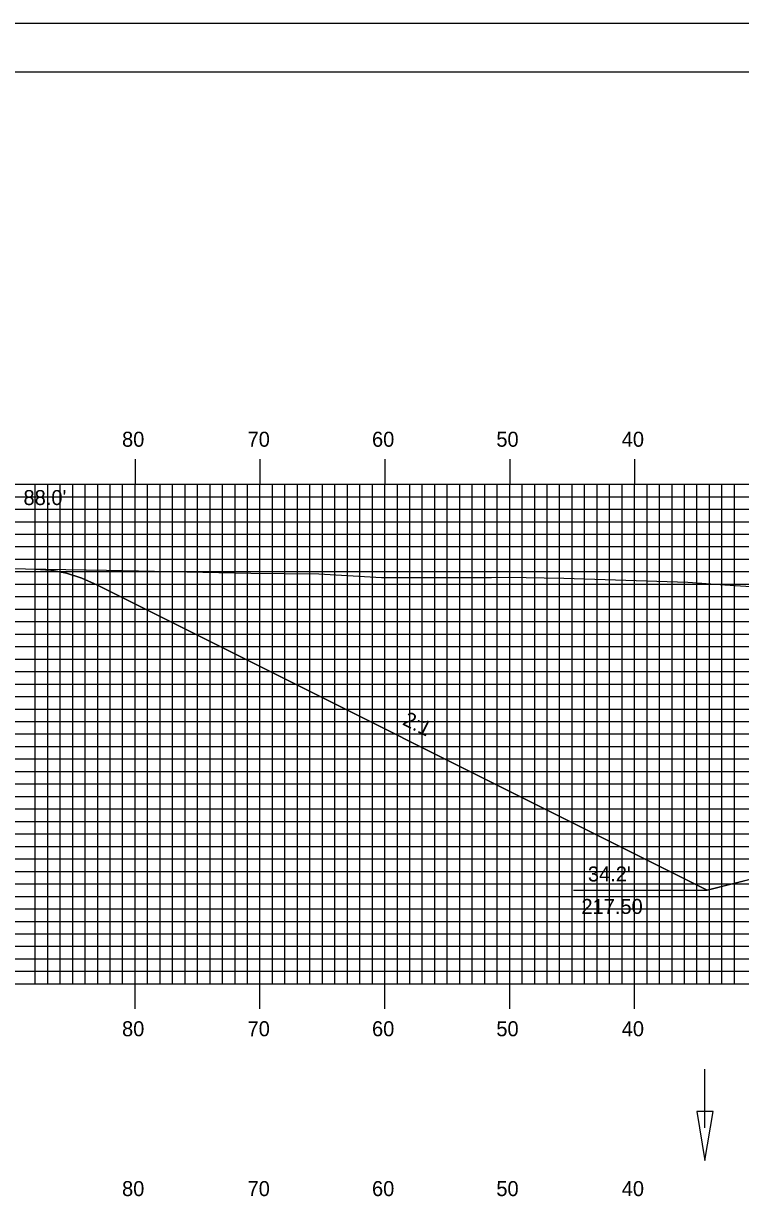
# Model space of a CAD drawing. Extents: x 1816489 to 1816833, y 442591 to 442811.
# Drawn here: x 1816566.1 to 1816623.6, y 442716.2 to 442810.5 of the extents above; entities that cross this region are included whole.
import ezdxf

# ---------------------------------------------------------------- set-up
doc = ezdxf.new("R2010")
doc.units = 0
for name, color, linetype in [('ANNOTATION', 7, 'Continuous'), ('BORDER', 7, 'Continuous'), ('D_Drainage_Ditch_Line', 7, 'Continuous'), ('D_Roadway_Centerline', 7, 'Continuous'), ('D_Roadway_SlopeLines', 7, 'Continuous'), ('D_Text_Standard', 7, 'Continuous'), ('H_V ANNOTATION', 7, 'Continuous'), ('MAJOR', 7, 'Continuous'), ('MINOR', 7, 'Continuous'), ('PDRAIN', 7, 'Continuous'), ('PLOT BOUNDARY', 7, 'Continuous'), ('S_Roadway_Centerline', 7, 'Continuous')]:
    doc.layers.add(name, color=color, linetype=linetype)

msp = doc.modelspace()

# ---------------------------------------------------------------- linework, layer by layer
at = {"layer": 'BORDER'}
msp.add_lwpolyline([(1816505.473, 442596.665), (1816825.473, 442596.665), (1816825.473, 442806.665), (1816505.473, 442806.665)], close=True, dxfattribs=at)
at = {"layer": 'D_Drainage_Ditch_Line'}
msp.add_line((1816620.707, 442722.133), (1816620.707, 442726.832), dxfattribs=at)
msp.add_lwpolyline([(1816621.363, 442723.445), (1816620.051, 442723.445), (1816620.707, 442719.508)], close=True, dxfattribs=at)
at = {"layer": 'D_Roadway_Centerline'}
msp.add_lwpolyline([(1816567.063, 442766.87), (1816568.313, 442766.776), (1816569.563, 442766.53), (1816570.813, 442766.133), (1816572.063, 442765.584), (1816620.899, 442741.166), (1816624.899, 442742.166), (1816635.073, 442744.709), (1816643.073, 442745.029), (1816655.073, 442745.269), (1816667.073, 442745.029), (1816675.073, 442744.709), (1816685.247, 442742.166), (1816689.247, 442741.166), (1816725.957, 442759.521), (1816727.207, 442760.056), (1816728.457, 442760.411), (1816729.707, 442760.586), (1816730.957, 442760.58)], dxfattribs=at)
at = {"layer": 'D_Roadway_SlopeLines'}
for points in [[(1816620.899, 442741.166), (1816572.063, 442765.584), (1816570.813, 442766.133), (1816569.563, 442766.53), (1816568.313, 442766.776), (1816567.063, 442766.87)], [(1816635.073, 442744.709), (1816620.899, 442741.166)]]:
    msp.add_lwpolyline(points, dxfattribs=at)
at = {"layer": 'MAJOR'}
for p, q in [((1816575.073, 442775.669), (1816575.073, 442773.665)), ((1816585.073, 442775.669), (1816585.073, 442773.665)), ((1816595.073, 442775.669), (1816595.073, 442773.665)), ((1816605.073, 442775.669), (1816605.073, 442773.665)), ((1816615.073, 442775.669), (1816615.073, 442773.665)), ((1816515.073, 442773.665), (1816795.073, 442773.665)), ((1816515.073, 442773.665), (1816795.073, 442773.665)), ((1816575.073, 442733.665), (1816575.073, 442773.665)), ((1816585.073, 442733.665), (1816585.073, 442773.665)), ((1816595.073, 442733.665), (1816595.073, 442773.665)), ((1816605.073, 442733.665), (1816605.073, 442773.665)), ((1816615.073, 442733.665), (1816615.073, 442773.665)), ((1816515.073, 442768.665), (1816795.073, 442768.665)), ((1816515.073, 442763.665), (1816795.073, 442763.665)), ((1816515.073, 442758.665), (1816795.073, 442758.665)), ((1816515.073, 442753.665), (1816795.073, 442753.665)), ((1816515.073, 442748.665), (1816795.073, 442748.665)), ((1816515.073, 442743.665), (1816795.073, 442743.665)), ((1816515.073, 442738.665), (1816795.073, 442738.665)), ((1816515.073, 442733.665), (1816795.073, 442733.665)), ((1816515.073, 442733.665), (1816795.073, 442733.665)), ((1816575.073, 442731.661), (1816575.073, 442733.665)), ((1816585.073, 442731.661), (1816585.073, 442733.665)), ((1816595.073, 442731.661), (1816595.073, 442733.665)), ((1816605.073, 442731.661), (1816605.073, 442733.665)), ((1816615.073, 442731.661), (1816615.073, 442733.665))]:
    msp.add_line(p, q, dxfattribs=at)
at = {"layer": 'MINOR'}
for p, q in [((1816567.073, 442733.665), (1816567.073, 442773.665)), ((1816568.073, 442733.665), (1816568.073, 442773.665)), ((1816569.073, 442733.665), (1816569.073, 442773.665)), ((1816570.073, 442733.665), (1816570.073, 442773.665)), ((1816571.073, 442733.665), (1816571.073, 442773.665)), ((1816572.073, 442733.665), (1816572.073, 442773.665)), ((1816573.073, 442733.665), (1816573.073, 442773.665)), ((1816574.073, 442733.665), (1816574.073, 442773.665)), ((1816576.073, 442733.665), (1816576.073, 442773.665)), ((1816577.073, 442733.665), (1816577.073, 442773.665)), ((1816578.073, 442733.665), (1816578.073, 442773.665)), ((1816579.073, 442733.665), (1816579.073, 442773.665)), ((1816580.073, 442733.665), (1816580.073, 442773.665)), ((1816581.073, 442733.665), (1816581.073, 442773.665)), ((1816582.073, 442733.665), (1816582.073, 442773.665)), ((1816583.073, 442733.665), (1816583.073, 442773.665)), ((1816584.073, 442733.665), (1816584.073, 442773.665)), ((1816586.073, 442733.665), (1816586.073, 442773.665)), ((1816587.073, 442733.665), (1816587.073, 442773.665)), ((1816588.073, 442733.665), (1816588.073, 442773.665)), ((1816589.073, 442733.665), (1816589.073, 442773.665)), ((1816590.073, 442733.665), (1816590.073, 442773.665)), ((1816591.073, 442733.665), (1816591.073, 442773.665)), ((1816592.073, 442733.665), (1816592.073, 442773.665)), ((1816593.073, 442733.665), (1816593.073, 442773.665)), ((1816594.073, 442733.665), (1816594.073, 442773.665)), ((1816596.073, 442733.665), (1816596.073, 442773.665)), ((1816597.073, 442733.665), (1816597.073, 442773.665)), ((1816598.073, 442733.665), (1816598.073, 442773.665)), ((1816599.073, 442733.665), (1816599.073, 442773.665)), ((1816600.073, 442733.665), (1816600.073, 442773.665)), ((1816601.073, 442733.665), (1816601.073, 442773.665)), ((1816602.073, 442733.665), (1816602.073, 442773.665)), ((1816603.073, 442733.665), (1816603.073, 442773.665)), ((1816604.073, 442733.665), (1816604.073, 442773.665)), ((1816606.073, 442733.665), (1816606.073, 442773.665)), ((1816607.073, 442733.665), (1816607.073, 442773.665)), ((1816608.073, 442733.665), (1816608.073, 442773.665)), ((1816609.073, 442733.665), (1816609.073, 442773.665)), ((1816610.073, 442733.665), (1816610.073, 442773.665)), ((1816611.073, 442733.665), (1816611.073, 442773.665)), ((1816612.073, 442733.665), (1816612.073, 442773.665)), ((1816613.073, 442733.665), (1816613.073, 442773.665)), ((1816614.073, 442733.665), (1816614.073, 442773.665)), ((1816616.073, 442733.665), (1816616.073, 442773.665)), ((1816617.073, 442733.665), (1816617.073, 442773.665)), ((1816618.073, 442733.665), (1816618.073, 442773.665)), ((1816619.073, 442733.665), (1816619.073, 442773.665)), ((1816620.073, 442733.665), (1816620.073, 442773.665)), ((1816621.073, 442733.665), (1816621.073, 442773.665)), ((1816622.073, 442733.665), (1816622.073, 442773.665)), ((1816623.073, 442733.665), (1816623.073, 442773.665)), ((1816515.073, 442772.665), (1816795.073, 442772.665)), ((1816515.073, 442771.665), (1816795.073, 442771.665)), ((1816515.073, 442770.665), (1816795.073, 442770.665)), ((1816515.073, 442769.665), (1816795.073, 442769.665)), ((1816515.073, 442767.665), (1816795.073, 442767.665)), ((1816515.073, 442766.665), (1816795.073, 442766.665)), ((1816515.073, 442765.665), (1816795.073, 442765.665)), ((1816515.073, 442764.665), (1816795.073, 442764.665)), ((1816515.073, 442762.665), (1816795.073, 442762.665)), ((1816515.073, 442761.665), (1816795.073, 442761.665)), ((1816515.073, 442760.665), (1816795.073, 442760.665)), ((1816515.073, 442759.665), (1816795.073, 442759.665)), ((1816515.073, 442757.665), (1816795.073, 442757.665)), ((1816515.073, 442756.665), (1816795.073, 442756.665)), ((1816515.073, 442755.665), (1816795.073, 442755.665)), ((1816515.073, 442754.665), (1816795.073, 442754.665)), ((1816515.073, 442752.665), (1816795.073, 442752.665)), ((1816515.073, 442751.665), (1816795.073, 442751.665)), ((1816515.073, 442750.665), (1816795.073, 442750.665)), ((1816515.073, 442749.665), (1816795.073, 442749.665)), ((1816515.073, 442747.665), (1816795.073, 442747.665)), ((1816515.073, 442746.665), (1816795.073, 442746.665)), ((1816515.073, 442745.665), (1816795.073, 442745.665)), ((1816515.073, 442744.665), (1816795.073, 442744.665)), ((1816515.073, 442742.665), (1816795.073, 442742.665)), ((1816515.073, 442741.665), (1816795.073, 442741.665)), ((1816515.073, 442740.665), (1816795.073, 442740.665)), ((1816515.073, 442739.665), (1816795.073, 442739.665)), ((1816515.073, 442737.665), (1816795.073, 442737.665)), ((1816515.073, 442736.665), (1816795.073, 442736.665)), ((1816515.073, 442735.665), (1816795.073, 442735.665)), ((1816515.073, 442734.665), (1816795.073, 442734.665))]:
    msp.add_line(p, q, dxfattribs=at)
at = {"layer": 'PDRAIN'}
msp.add_line((1816610.176, 442741.166), (1816620.899, 442741.166), dxfattribs=at)
at = {"layer": 'PLOT BOUNDARY'}
msp.add_lwpolyline([(1816489.286, 442590.547), (1816829.286, 442590.547), (1816829.286, 442810.547), (1816489.286, 442810.547)], close=True, dxfattribs=at)
at = {"layer": 'S_Roadway_Centerline'}
msp.add_lwpolyline([(1816564.673, 442766.905), (1816572.774, 442766.787), (1816584.332, 442766.552), (1816589.797, 442766.489), (1816594.798, 442766.207), (1816598.124, 442766.206), (1816603.619, 442766.208), (1816604.947, 442766.213), (1816607.835, 442766.159), (1816609.418, 442766.149), (1816619.351, 442765.83), (1816622.294, 442765.621), (1816628.188, 442765.242)], dxfattribs=at)

# ---------------------------------------------------------------- texts
at = {"layer": 'ANNOTATION'}
msp.add_text('2:1', height=1.2, rotation=333.43495, dxfattribs=at).set_placement((1816596.415, 442754.444))
for s, p in [("34.2'", (1816611.337, 442741.858)), ('217.50', (1816610.818, 442739.258))]:
    msp.add_text(s, height=1.2, dxfattribs=at).set_placement(p)
at = {"layer": 'D_Text_Standard'}
msp.add_text("88.0'", height=1.2, dxfattribs=at).set_placement((1816566.131, 442771.996))
at = {"layer": 'H_V ANNOTATION'}
for s, p in [('80', (1816574.024, 442776.665)), ('70', (1816584.077, 442776.665)), ('60', (1816594.045, 442776.665)), ('50', (1816604.002, 442776.665)), ('40', (1816614.045, 442776.665)), ('80', (1816574.024, 442729.465)), ('70', (1816584.077, 442729.465)), ('60', (1816594.045, 442729.465)), ('50', (1816604.002, 442729.465)), ('40', (1816614.045, 442729.465)), ('80', (1816574.024, 442716.665)), ('70', (1816584.077, 442716.665)), ('60', (1816594.045, 442716.665)), ('50', (1816604.002, 442716.665)), ('40', (1816614.045, 442716.665))]:
    msp.add_text(s, height=1.2, dxfattribs=at).set_placement(p)

doc.saveas('drawing.dxf')
